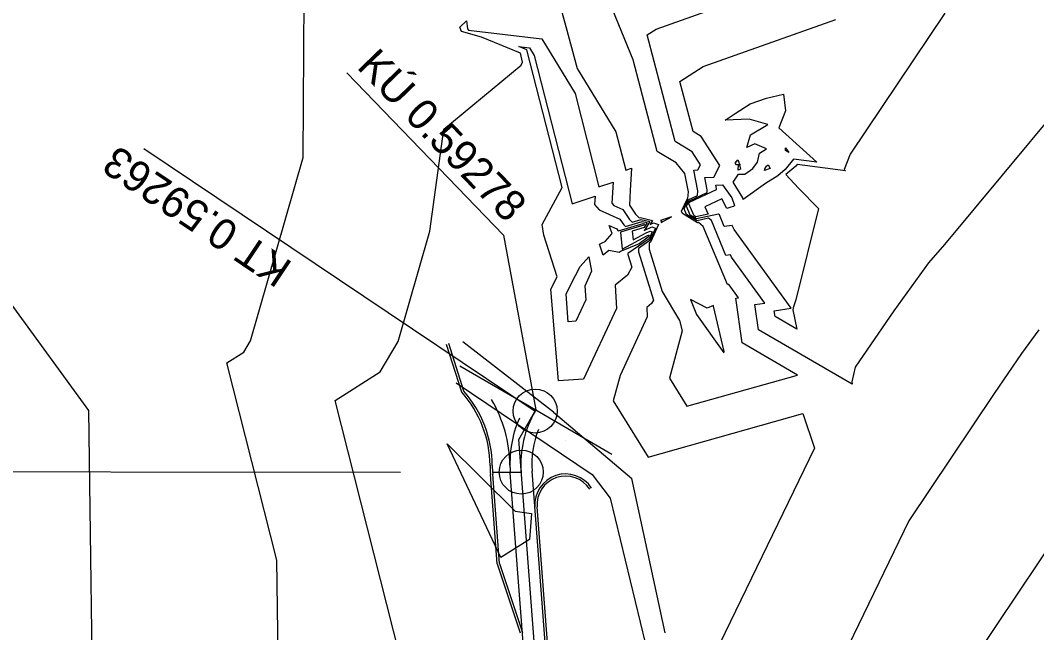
# Model space of a CAD drawing. Extents: x -549394 to -546608, y -1037055 to -1033629.
# Drawn here: x -547938.3 to -547822.8, y -1034649.2 to -1034579.6 of the extents above; entities that cross this region are included whole.
import ezdxf

# ---------------------------------------------------------------- set-up
doc = ezdxf.new("R2010")
doc.units = 0
for name, color, linetype in [('hlavni_vrst', 7, 'Continuous'), ('hrana_L', 7, 'Continuous'), ('norm_vrst', 7, 'Continuous'), ('POLYGONY_SITUACE_PO', 7, 'Continuous'), ('x_navrh_C121', 7, 'Continuous'), ('x_osa_C121', 7, 'Continuous'), ('x_popis_oblouky_C121', 7, 'Continuous'), ('x_popis_pricne_rezy_C121', 7, 'Continuous')]:
    doc.layers.add(name, color=color, linetype=linetype)

msp = doc.modelspace()

# ---------------------------------------------------------------- linework, layer by layer
at = {"layer": 'hlavni_vrst'}
for p, q in [((-547855.39, -1034589.11), (-547853.52, -1034588.45)), ((-547853.52, -1034588.45), (-547851.59, -1034588.02)), ((-547851.59, -1034588.02), (-547851.38, -1034589.9)), ((-547857.11, -1034590.21), (-547855.39, -1034589.11)), ((-547858.22, -1034590.96), (-547857.11, -1034590.21)), ((-547851.38, -1034589.9), (-547852.13, -1034591.83)), ((-547855.5, -1034590.85), (-547858.22, -1034590.96)), ((-547853.38, -1034591.44), (-547855.5, -1034590.85)), ((-547855.35, -1034592.64), (-547853.38, -1034591.44)), ((-547852.13, -1034591.83), (-547847.81, -1034595.73)), ((-547855.76, -1034594.07), (-547855.35, -1034592.64)), ((-547854.86, -1034593.64), (-547855.76, -1034594.07)), ((-547853.54, -1034594.23), (-547854.86, -1034593.64)), ((-547854.35, -1034594.72), (-547853.54, -1034594.23)), ((-547854.55, -1034595.72), (-547854.35, -1034594.72)), ((-547850.46, -1034595.39), (-547851.43, -1034596.58)), ((-547847.81, -1034595.73), (-547850.46, -1034595.39)), ((-547857.09, -1034595.86), (-547856.79, -1034595.47)), ((-547856.93, -1034596.05), (-547857.09, -1034595.86)), ((-547856.67, -1034596.02), (-547856.93, -1034596.05)), ((-547856.79, -1034595.47), (-547856.67, -1034595.74)), ((-547856.75, -1034596.43), (-547856.67, -1034596.02)), ((-547856.75, -1034596.62), (-547856.75, -1034596.43)), ((-547856.51, -1034596.53), (-547856.75, -1034596.62)), ((-547856.67, -1034595.74), (-547856.63, -1034595.97)), ((-547856.63, -1034595.97), (-547856.54, -1034595.99)), ((-547856.54, -1034595.99), (-547856.61, -1034596.04)), ((-547856.61, -1034596.04), (-547856.51, -1034596.53)), ((-547855.99, -1034597.1), (-547855.08, -1034596.46)), ((-547855.08, -1034596.46), (-547854.55, -1034595.72)), ((-547851.43, -1034596.58), (-547852.25, -1034597.27)), ((-547857.31, -1034598.01), (-547856.71, -1034597.1)), ((-547856.71, -1034597.1), (-547855.99, -1034597.1)), ((-547852.25, -1034597.27), (-547853.65, -1034598.14)), ((-547862.27, -1034600.28), (-547859.21, -1034598.83)), ((-547859.29, -1034598.34), (-547858.54, -1034598.29)), ((-547859.21, -1034598.74), (-547859.29, -1034598.34)), ((-547859.21, -1034598.83), (-547859.21, -1034598.74)), ((-547858.54, -1034598.29), (-547857.47, -1034599.77)), ((-547856.22, -1034599.79), (-547857.31, -1034598.01)), ((-547853.65, -1034598.14), (-547856.17, -1034599.98)), ((-547858.62, -1034599.9), (-547860.55, -1034600.8)), ((-547858.05, -1034601.01), (-547858.62, -1034599.9)), ((-547857.47, -1034599.77), (-547857.18, -1034600.64)), ((-547856.17, -1034599.98), (-547856.22, -1034599.79)), ((-547862.35, -1034600.45), (-547862.27, -1034600.28)), ((-547861.77, -1034601.83), (-547862.35, -1034600.45)), ((-547860.55, -1034600.8), (-547860.17, -1034601.64)), ((-547857.6, -1034600.85), (-547858.05, -1034601.01)), ((-547857.3, -1034600.78), (-547857.6, -1034600.85)), ((-547857.18, -1034600.64), (-547857.3, -1034600.78)), ((-547861.56, -1034601.95), (-547861.77, -1034601.83)), ((-547860.17, -1034601.64), (-547861.56, -1034601.95)), ((-547871.41, -1034602.91), (-547870.53, -1034603.29)), ((-547871.07, -1034603.84), (-547871.41, -1034602.91)), ((-547870.53, -1034603.29), (-547870.41, -1034603.48)), ((-547870.41, -1034603.48), (-547870.36, -1034603.52)), ((-547870.36, -1034603.52), (-547867.54, -1034602.68)), ((-547867.48, -1034602.88), (-547870.14, -1034603.67)), ((-547867.54, -1034602.68), (-547867.38, -1034602.72)), ((-547867.38, -1034602.72), (-547867.48, -1034602.88)), ((-547871.87, -1034604.75), (-547871.07, -1034603.84)), ((-547870.14, -1034603.67), (-547869.95, -1034605.6)), ((-547869.95, -1034605.6), (-547867.06, -1034604.07)), ((-547866.97, -1034604.26), (-547868.02, -1034604.99)), ((-547867.06, -1034604.07), (-547866.93, -1034604.01)), ((-547866.86, -1034604.03), (-547866.97, -1034604.26)), ((-547866.93, -1034604.01), (-547866.86, -1034604.03)), ((-547872.51, -1034605.03), (-547872.22, -1034604.89)), ((-547872.11, -1034606.3), (-547872.51, -1034605.03)), ((-547872.22, -1034604.89), (-547871.87, -1034604.75)), ((-547871.44, -1034605.75), (-547872.11, -1034606.3)), ((-547870.26, -1034606.01), (-547871.44, -1034605.75)), ((-547868.02, -1034604.99), (-547870.06, -1034605.85)), ((-547874.72, -1034607.57), (-547873.72, -1034606.48)), ((-547873.72, -1034606.48), (-547873.4, -1034608.13)), ((-547870.06, -1034605.85), (-547870.26, -1034606.01)), ((-547875.77, -1034609.63), (-547874.72, -1034607.57)), ((-547873.4, -1034608.13), (-547874.17, -1034609.82)), ((-547876.31, -1034610.73), (-547875.77, -1034609.63)), ((-547874.17, -1034609.82), (-547874.08, -1034611.38)), ((-547876.06, -1034613.86), (-547876.31, -1034610.73)), ((-547874.08, -1034611.38), (-547875.2, -1034613.8)), ((-547875.2, -1034613.8), (-547876.06, -1034613.86))]:
    msp.add_line(p, q, dxfattribs=at)
at = {"layer": 'hrana_L'}
for p, q in [((-547877.75, -1034624.13), (-547888.02, -1034616.15)), ((-547888.78, -1034620.79), (-547873.35, -1034631.21)), ((-547877.75, -1034624.13), (-547868.85, -1034631.65)), ((-547873.35, -1034631.21), (-547871.3, -1034633.92)), ((-547865.04, -1034649.22), (-547868.85, -1034631.65)), ((-547871.3, -1034633.92), (-547867.33, -1034650.32))]:
    msp.add_line(p, q, dxfattribs=at)
at = {"layer": 'norm_vrst'}
for p, q in [((-547906.18, -1034595.2), (-547906.03, -1034574.52)), ((-547877.04, -1034577.71), (-547876.33, -1034580.33)), ((-547868.69, -1034584.09), (-547871.01, -1034578.47)), ((-547866.08, -1034580.63), (-547860.31, -1034578.59)), ((-547833.27, -1034578.79), (-547844.05, -1034594.82)), ((-547888.36, -1034580.39), (-547887.63, -1034579.69)), ((-547888.19, -1034580.88), (-547888.36, -1034580.39)), ((-547887.63, -1034579.69), (-547887.52, -1034580.57)), ((-547876.33, -1034580.33), (-547875.03, -1034585.08)), ((-547860.73, -1034584.87), (-547845.65, -1034579.54)), ((-547812.36, -1034579.85), (-547833.3, -1034605.08)), ((-547885.9, -1034581.53), (-547888.19, -1034580.88)), ((-547887.52, -1034580.57), (-547887.38, -1034580.75)), ((-547887.38, -1034580.75), (-547879.07, -1034581.73)), ((-547881.5, -1034583.33), (-547885.9, -1034581.53)), ((-547867.09, -1034581.27), (-547866.08, -1034580.63)), ((-547863.92, -1034593.38), (-547867.09, -1034581.27)), ((-547880.78, -1034582.97), (-547881.68, -1034582.6)), ((-547881.68, -1034582.6), (-547880.45, -1034582.75)), ((-547880.45, -1034582.75), (-547879.93, -1034583.6)), ((-547879.07, -1034581.73), (-547875.29, -1034587.94)), ((-547881.24, -1034584.36), (-547881.5, -1034583.33)), ((-547876.75, -1034598.6), (-547880.78, -1034582.97)), ((-547879.93, -1034583.6), (-547875.62, -1034600.45)), ((-547890.21, -1034591.99), (-547881.42, -1034584.7)), ((-547881.42, -1034584.7), (-547881.24, -1034584.36)), ((-547865.97, -1034594.51), (-547868.69, -1034584.09)), ((-547863.37, -1034586.55), (-547860.73, -1034584.87)), ((-547875.03, -1034585.08), (-547870.65, -1034592.27)), ((-547861.88, -1034592.25), (-547863.37, -1034586.55)), ((-547875.29, -1034587.94), (-547872.58, -1034598.54)), ((-547891.8, -1034603.57), (-547890.21, -1034591.99)), ((-547870.65, -1034592.27), (-547869.53, -1034596.64)), ((-547860.97, -1034592.8), (-547861.88, -1034592.25)), ((-547858.85, -1034596.1), (-547860.97, -1034592.8)), ((-547861.99, -1034594.54), (-547863.92, -1034593.38)), ((-547851.39, -1034594.11), (-547850.99, -1034594.65)), ((-547851.38, -1034594.39), (-547851.39, -1034594.11)), ((-547912.15, -1034616.02), (-547906.18, -1034595.2)), ((-547863.8, -1034595.81), (-547865.97, -1034594.51)), ((-547861.04, -1034596.02), (-547861.99, -1034594.54)), ((-547850.99, -1034594.65), (-547851.38, -1034594.39)), ((-547844.05, -1034594.82), (-547844.73, -1034596.56)), ((-547869.53, -1034596.64), (-547868.86, -1034596.41)), ((-547868.86, -1034596.41), (-547869.02, -1034598.96)), ((-547862.82, -1034597.02), (-547863.8, -1034595.81)), ((-547861.35, -1034596.61), (-547861.04, -1034596.02)), ((-547859.53, -1034597.42), (-547858.85, -1034596.1)), ((-547853.12, -1034596.46), (-547853.77, -1034596.68)), ((-547853.77, -1034596.68), (-547853.74, -1034596.49)), ((-547853.74, -1034596.49), (-547853.52, -1034596.18)), ((-547853.52, -1034596.18), (-547853.51, -1034596.13)), ((-547853.51, -1034596.13), (-547853.36, -1034596.03)), ((-547853.36, -1034596.03), (-547853.12, -1034596.46)), ((-547850.22, -1034596.18), (-547851.35, -1034597.13)), ((-547850.07, -1034595.99), (-547850.22, -1034596.18)), ((-547844.56, -1034596.71), (-547850.07, -1034595.99)), ((-547844.73, -1034596.56), (-547844.56, -1034596.71)), ((-547862.4, -1034599.1), (-547862.82, -1034597.02)), ((-547861.8, -1034596.64), (-547861.35, -1034596.61)), ((-547861.34, -1034598.98), (-547861.8, -1034596.64)), ((-547860.54, -1034597.49), (-547859.53, -1034597.42)), ((-547860.27, -1034598.86), (-547860.54, -1034597.49)), ((-547851.35, -1034597.13), (-547849.91, -1034598.68)), ((-547879.03, -1034602.8), (-547876.75, -1034598.6)), ((-547872.58, -1034598.54), (-547870.94, -1034598)), ((-547870.94, -1034598), (-547871.09, -1034600.38)), ((-547860.29, -1034599.17), (-547860.27, -1034598.86)), ((-547849.91, -1034598.68), (-547847.64, -1034601.01)), ((-547875.62, -1034600.45), (-547873.02, -1034599.6)), ((-547873.02, -1034599.6), (-547873.08, -1034600.53)), ((-547869.02, -1034598.96), (-547869.11, -1034600.61)), ((-547863.18, -1034601.31), (-547862.51, -1034599.87)), ((-547862.9, -1034601.03), (-547862.43, -1034600.01)), ((-547862.51, -1034599.87), (-547862.46, -1034599.84)), ((-547862.46, -1034599.84), (-547862.4, -1034599.1)), ((-547862.43, -1034600.01), (-547861.38, -1034599.5)), ((-547862.35, -1034600.15), (-547860.29, -1034599.17)), ((-547861.38, -1034599.5), (-547861.34, -1034598.98)), ((-547873.08, -1034600.53), (-547872.55, -1034601.16)), ((-547872.55, -1034601.16), (-547870.19, -1034602.19)), ((-547871.09, -1034600.38), (-547870.87, -1034600.65)), ((-547870.87, -1034600.65), (-547869.85, -1034601.09)), ((-547869.85, -1034601.09), (-547869.09, -1034602.25)), ((-547869.11, -1034600.61), (-547868.43, -1034601.64)), ((-547862.63, -1034601.66), (-547862.9, -1034601.03)), ((-547862.63, -1034600.74), (-547862.35, -1034600.15)), ((-547862.2, -1034601.74), (-547862.63, -1034600.74)), ((-547847.64, -1034601.01), (-547850.19, -1034611.37)), ((-547870.19, -1034602.19), (-547869.75, -1034602.86)), ((-547869.09, -1034602.25), (-547868.79, -1034602.55)), ((-547868.79, -1034602.55), (-547867.76, -1034602.24)), ((-547868.43, -1034601.64), (-547868, -1034602.06)), ((-547868, -1034602.06), (-547867.86, -1034602.02)), ((-547867.86, -1034602.02), (-547866.49, -1034602.37)), ((-547867.76, -1034602.24), (-547866.79, -1034602.48)), ((-547866.49, -1034602.37), (-547866.76, -1034602.8)), ((-547864.33, -1034601.93), (-547865.57, -1034602.37)), ((-547865.57, -1034602.37), (-547865.44, -1034602.41)), ((-547865.49, -1034602.6), (-547864.33, -1034601.93)), ((-547863.07, -1034601.58), (-547863.18, -1034601.31)), ((-547861.37, -1034602.61), (-547863.07, -1034601.58)), ((-547861.43, -1034602.39), (-547862.63, -1034601.66)), ((-547861.5, -1034602.17), (-547862.2, -1034601.74)), ((-547858.99, -1034601.62), (-547861.5, -1034602.17)), ((-547860.12, -1034602.1), (-547861.43, -1034602.39)), ((-547859.8, -1034602.37), (-547860.12, -1034602.1)), ((-547858.15, -1034606.33), (-547859.8, -1034602.37)), ((-547858.89, -1034601.71), (-547858.99, -1034601.62)), ((-547858.34, -1034603.03), (-547858.89, -1034601.71)), ((-547878.82, -1034604.04), (-547879.03, -1034602.8)), ((-547869.75, -1034602.86), (-547869.57, -1034603.04)), ((-547869.57, -1034603.04), (-547867.65, -1034602.46)), ((-547867.42, -1034603.15), (-547868.79, -1034603.55)), ((-547867.65, -1034602.46), (-547867.08, -1034602.6)), ((-547867.36, -1034603.42), (-547867.43, -1034603.44)), ((-547867.43, -1034603.44), (-547867.42, -1034603.48)), ((-547867.08, -1034602.6), (-547867.42, -1034603.15)), ((-547867.42, -1034603.48), (-547867.35, -1034603.45)), ((-547866.79, -1034602.48), (-547867.36, -1034603.42)), ((-547867.35, -1034603.45), (-547866.57, -1034603.09)), ((-547866.15, -1034603.22), (-547866.79, -1034604.64)), ((-547866.76, -1034602.8), (-547866.39, -1034602.64)), ((-547865.8, -1034602.81), (-547866.7, -1034604.83)), ((-547866.57, -1034603.09), (-547866.15, -1034603.22)), ((-547866.39, -1034602.64), (-547865.8, -1034602.81)), ((-547865.44, -1034602.41), (-547865.49, -1034602.5)), ((-547865.49, -1034602.5), (-547865.49, -1034602.6)), ((-547861.25, -1034602.58), (-547861.37, -1034602.61)), ((-547860.72, -1034603.02), (-547861.25, -1034602.58)), ((-547857.97, -1034609.62), (-547860.72, -1034603.02)), ((-547857.43, -1034602.92), (-547858.34, -1034603.03)), ((-547857.22, -1034603.37), (-547857.43, -1034602.92)), ((-547850.74, -1034612.33), (-547857.22, -1034603.37)), ((-547895.39, -1034616.11), (-547891.8, -1034603.57)), ((-547877.33, -1034608.76), (-547878.82, -1034604.04)), ((-547866.88, -1034604.45), (-547869.28, -1034606.1)), ((-547868.79, -1034603.55), (-547868.69, -1034604.54)), ((-547868.69, -1034604.54), (-547867.21, -1034603.76)), ((-547866.79, -1034604.64), (-547868.07, -1034605.52)), ((-547867.21, -1034603.76), (-547866.75, -1034603.55)), ((-547866.51, -1034603.63), (-547866.88, -1034604.45)), ((-547866.75, -1034603.55), (-547866.51, -1034603.63)), ((-547868.07, -1034605.52), (-547868.08, -1034605.91)), ((-547866.85, -1034604.93), (-547866.87, -1034605.62)), ((-547866.87, -1034605.62), (-547865.4, -1034610.42)), ((-547866.7, -1034604.83), (-547866.85, -1034604.93)), ((-547833.3, -1034605.08), (-547835.14, -1034607.17)), ((-547869.28, -1034606.1), (-547869.29, -1034606.21)), ((-547869.29, -1034606.21), (-547868.85, -1034607.64)), ((-547868.08, -1034605.91), (-547866.39, -1034611.42)), ((-547857.63, -1034606.27), (-547858.15, -1034606.33)), ((-547857.51, -1034606.52), (-547857.63, -1034606.27)), ((-547853.74, -1034611.73), (-547857.51, -1034606.52)), ((-547868.85, -1034607.64), (-547869.34, -1034608.56)), ((-547835.14, -1034607.17), (-547839.08, -1034612.61)), ((-547878.02, -1034610.16), (-547877.33, -1034608.76)), ((-547869.34, -1034608.56), (-547870.73, -1034609.7)), ((-547877.16, -1034620.57), (-547878.02, -1034610.16)), ((-547870.73, -1034609.7), (-547870.58, -1034612.35)), ((-547865.4, -1034610.42), (-547863.43, -1034613.73)), ((-547857.82, -1034609.61), (-547857.97, -1034609.62)), ((-547857.79, -1034609.68), (-547857.82, -1034609.61)), ((-547856.73, -1034611.14), (-547857.79, -1034609.68)), ((-547866.39, -1034611.42), (-547866.59, -1034611.79)), ((-547860.29, -1034612.3), (-547862.19, -1034611.32)), ((-547862.19, -1034611.32), (-547861.5, -1034613.04)), ((-547857.04, -1034611.19), (-547856.73, -1034611.14)), ((-547856.32, -1034616.26), (-547857.04, -1034611.19)), ((-547850.19, -1034611.37), (-547850.5, -1034612.28)), ((-547930.54, -1034623.95), (-547939.34, -1034611.82)), ((-547870.58, -1034612.35), (-547874.32, -1034620.37)), ((-547866.59, -1034611.79), (-547867.14, -1034612.25)), ((-547867.14, -1034612.25), (-547867.08, -1034613.31)), ((-547859.57, -1034612.02), (-547860.29, -1034612.3)), ((-547859.55, -1034612.1), (-547859.57, -1034612.02)), ((-547858.33, -1034617.24), (-547859.55, -1034612.1)), ((-547854.85, -1034611.9), (-547853.74, -1034611.73)), ((-547854.44, -1034614.76), (-547854.85, -1034611.9)), ((-547852.65, -1034612.61), (-547850.74, -1034612.33)), ((-547852.56, -1034613.27), (-547852.65, -1034612.61)), ((-547850.5, -1034612.28), (-547850.55, -1034612.5)), ((-547850.55, -1034612.5), (-547850.1, -1034614.7)), ((-547839.08, -1034612.61), (-547843.48, -1034619.01)), ((-547867.08, -1034613.31), (-547870.18, -1034619.95)), ((-547863.43, -1034613.73), (-547863.1, -1034614.91)), ((-547861.5, -1034613.04), (-547858.39, -1034617.41)), ((-547850.1, -1034614.7), (-547852.56, -1034613.27)), ((-547863.1, -1034614.91), (-547864.54, -1034620.27)), ((-547843.8, -1034620.95), (-547854.44, -1034614.76)), ((-547822.61, -1034614.79), (-547824.57, -1034617.48)), ((-547912.92, -1034617.31), (-547912.15, -1034616.02)), ((-547897.44, -1034619.54), (-547895.39, -1034616.11)), ((-547914.83, -1034618.53), (-547912.92, -1034617.31)), ((-547858.39, -1034617.41), (-547858.33, -1034617.24)), ((-547850.02, -1034619.92), (-547856.32, -1034616.26)), ((-547909.16, -1034640.94), (-547914.83, -1034618.53)), ((-547824.57, -1034617.48), (-547827.69, -1034622.02)), ((-547902.54, -1034622.79), (-547897.44, -1034619.54)), ((-547843.48, -1034619.01), (-547843.86, -1034620.68)), ((-547874.32, -1034620.37), (-547877.16, -1034620.57)), ((-547870.18, -1034619.95), (-547870.95, -1034622.83)), ((-547864.54, -1034620.27), (-547862.57, -1034623.45)), ((-547862.57, -1034623.45), (-547850.02, -1034619.92)), ((-547843.86, -1034620.68), (-547843.8, -1034620.95)), ((-547888.82, -1034677.02), (-547902.54, -1034622.79)), ((-547870.95, -1034622.83), (-547866.99, -1034629.23)), ((-547827.69, -1034622.02), (-547837.37, -1034636.49)), ((-547929.91, -1034668.08), (-547930.54, -1034623.95)), ((-547866.99, -1034629.23), (-547849.4, -1034624.28)), ((-547849.4, -1034624.28), (-547848.08, -1034628.21)), ((-547812.8, -1034626.46), (-547830.92, -1034653.55)), ((-547883.7, -1034640.65), (-547889.81, -1034627.72)), ((-547889.81, -1034627.72), (-547882.08, -1034635.38)), ((-547848.08, -1034628.21), (-547858.84, -1034650.41)), ((-547882.08, -1034635.38), (-547880.23, -1034635.63)), ((-547880.23, -1034635.63), (-547880.46, -1034638.58)), ((-547837.37, -1034636.49), (-547845.37, -1034652.99)), ((-547880.46, -1034638.58), (-547883.7, -1034640.65)), ((-547908.68, -1034674.25), (-547909.16, -1034640.94))]:
    msp.add_line(p, q, dxfattribs=at)
at = {"layer": 'POLYGONY_SITUACE_PO'}
for centre in [(-547879.82, -1034624), (-547881.4, -1034630.94)]:
    msp.add_circle(centre, 2.5, dxfattribs=at)
at = {"layer": 'x_navrh_C121'}
for p, q in [((-547888.14, -1034621.87), (-547889.88, -1034616.43)), ((-547887.92, -1034621.75), (-547889.64, -1034616.33)), ((-547884.12, -1034641.38), (-547884.89, -1034631.2)), ((-547883.87, -1034641.33), (-547884.64, -1034631.18)), ((-547873.48, -1034751.46), (-547882.65, -1034631.03)), ((-547870.99, -1034751.27), (-547880.16, -1034630.84)), ((-547884.12, -1034641.38), (-547881.52, -1034649.21))]:
    msp.add_line(p, q, dxfattribs=at)
for points in [[(-547870.74, -1034751.25), (-547879.6, -1034634.9)], [(-547883.87, -1034641.33), (-547881.27, -1034649.16), (-547881.27, -1034649.16)]]:
    msp.add_lwpolyline(points, dxfattribs=at)
for centre, radius, start, end in [((-547897.69, -1034630.33), 12.75, 0.6126, 41.5378), ((-547897.69, -1034630.33), 13, 0.6126, 41.3038), ((-547897.69, -1034630.33), 15, 0.6126, 30.5383), ((-547869.44, -1034630.03), 13.25, 156.753, 184.3542), ((-547869.44, -1034630.03), 10.75, 158.5796, 184.3542), ((-547873.74, -1034623.11), 5, 238.9655, 238.9656), ((-547869.44, -1034630.03), 15.5, 180.6126, 184.3542), ((-547869.44, -1034630.03), 15.25, 180.6126, 184.3542), ((-547884.89, -1034631.2), 5, 4.3542, 4.3545)]:
    msp.add_arc(centre, radius, start, end, dxfattribs=at)
at = {"layer": 'x_osa_C121'}
msp.add_lwpolyline([(-547871.32, -1034763.38), (-547881.69, -1034627.22), (-547879.74, -1034623.88)], dxfattribs=at)
msp.add_arc((-547869.44, -1034630.03), 12, 149.8721, 184.3542, dxfattribs=at)
at = {"layer": 'x_popis_oblouky_C121'}
msp.add_line((-547883.4, -1034604.04), (-547879.74, -1034623.88), dxfattribs=at)
for points in [[(-547901.22, -1034585.59), (-547883.4, -1034604.04)], [(-547924.27, -1034594.16), (-547879.82, -1034624)], [(-547961.01, -1034630.88), (-547895.1, -1034630.93)], [(-547884.59, -1034630.94), (-547881.4, -1034630.94)]]:
    msp.add_lwpolyline(points, dxfattribs=at)
for radius in [3.5, 3.25]:
    msp.add_arc((-547876.36, -1034634.65), radius, 32.6965, 184.3542, dxfattribs=at)
at = {"layer": 'x_popis_pricne_rezy_C121'}
msp.add_lwpolyline([(-547888.39, -1034618.86), (-547879.74, -1034623.88), (-547871.09, -1034628.9)], dxfattribs=at)

# ---------------------------------------------------------------- texts
at = {"layer": 'x_popis_oblouky_C121'}
for s, rotation, p in [('KÚ 0.59278', 314.0071, (-547900.2, -1034584.97)), ('KT 0.59263', 146.1199, (-547907.23, -1034607.21))]:
    msp.add_text(s, height=3.5, rotation=rotation, dxfattribs=at).set_placement(p)

doc.saveas('drawing.dxf')
